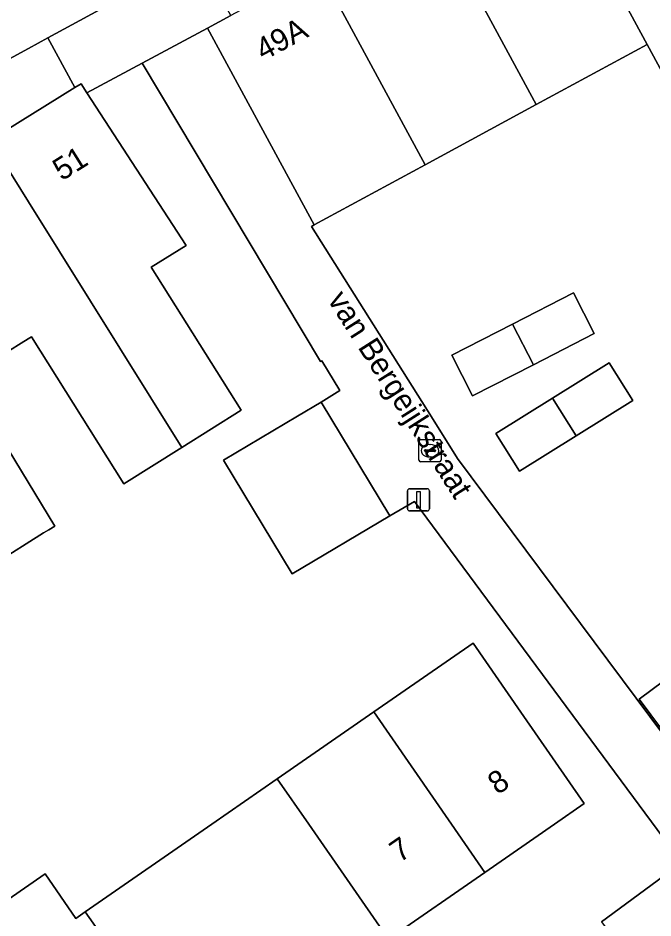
# Model space of a CAD drawing. Extents: x 161798 to 162385, y 382315 to 382833.
# Drawn here: x 161999.53 to 162028.08, y 382495.78 to 382536.26 of the extents above; entities that cross this region are included whole.
import ezdxf

# ---------------------------------------------------------------- set-up
doc = ezdxf.new("R2010")
doc.units = 0
for name, color, linetype in [('IMGEO_Erf', 7, 'Continuous'), ('IMGEO_Kolk', 7, 'Continuous'), ('IMGEO_Lichtmast', 7, 'Continuous'), ('IMGEO_Openbare_ruimte_label', 7, 'Continuous'), ('IMGEO_Pand', 7, 'Continuous'), ('IMGEO_Pand_nummerreeks', 7, 'Continuous'), ('IMGEO_Rijbaan_lokaal_open', 7, 'Continuous'), ('IMGEO_Voetpad_open', 7, 'Continuous')]:
    doc.layers.add(name, color=color, linetype=linetype)

msp = doc.modelspace()

# ---------------------------------------------------------------- linework, layer by layer
at = {"layer": 'IMGEO_Erf'}
for points in [[(162030.144, 382530.776), (162027.822, 382535.062), (162022.829, 382532.361), (162017.835, 382529.66), (162012.842, 382526.959), (162012.729, 382526.884), (162018.127, 382518.324), (162019.294, 382516.448), (162033.46, 382497.424)], [(162032.099, 382494.574), (162017.357, 382514.511), (162016.252, 382513.875), (162011.864, 382511.26), (162008.769, 382516.37), (162012.091, 382518.35), (162013.157, 382518.985), (162014.004, 382519.503), (162013.198, 382520.835), (162013.13, 382520.802), (162005.114, 382534.226), (162002.633, 382532.892), (162007.095, 382526.032), (162005.526, 382525.045), (162009.567, 382518.617), (162006.904, 382516.943), (162004.293, 382515.302), (162000.143, 382521.924), (161999.985, 382521.825), (161999.68, 382521.633), (161998.618, 382520.967)], [(161997.572, 382519.339), (162001.183, 382513.409), (162000.921, 382513.244), (162000.686, 382513.097), (161998.485, 382511.718)], [(162033.521, 382497.469), (162027.455, 382505.625), (162031.195, 382508.4)], [(162025.765, 382495.613), (162028.834, 382497.868)]]:
    msp.add_lwpolyline(points, dxfattribs=at)
for points in [[(162019.03, 382521.09), (162021.767, 382522.49), (162024.504, 382523.89), (162025.438, 382522.064), (162022.701, 382520.664), (162019.964, 382519.264)], [(162024.623, 382517.461), (162022.075, 382515.869), (162021.016, 382517.565), (162023.563, 382519.157), (162026.112, 382520.75), (162027.17, 382519.053)], [(161996.867, 382495.078), (162000.748, 382497.765), (162002.132, 382495.765), (162002.559, 382496.061), (162008.247, 382500), (162011.191, 382502.039), (162015.531, 382505.046), (162019.993, 382508.136), (162022.139, 382505.038), (162024.987, 382500.927), (162023.649, 382500), (162020.522, 382497.834), (162016.181, 382494.828), (162013.781, 382493.165), (162014.653, 382491.905), (162010.774, 382489.218), (162009.894, 382490.488), (162007.543, 382488.859), (162003.252, 382485.887), (161998.668, 382482.712), (161992.22, 382491.86)]]:
    msp.add_lwpolyline(points, close=True, dxfattribs=at)
at = {"layer": 'IMGEO_Kolk'}
for p, q in [((162017.628, 382517.297), (162018.48, 382517.297)), ((162017.553, 382516.371), (162017.553, 382517.223)), ((162018.041, 382517.077), (162018.066, 382517.077)), ((162018.554, 382517.223), (162018.554, 382516.371)), ((162017.812, 382516.791), (162017.812, 382516.803)), ((162018.25, 382516.754), (162017.852, 382516.754)), ((162017.855, 382516.84), (162018.253, 382516.84)), ((162018.064, 382516.517), (162018.039, 382516.517)), ((162018.296, 382516.803), (162018.296, 382516.791)), ((162018.48, 382516.297), (162017.628, 382516.297))]:
    msp.add_line(p, q, dxfattribs=at)
for points in [[(162017.628, 382517.297), (162018.48, 382517.297)], [(162017.553, 382516.371), (162017.553, 382517.223)], [(162018.554, 382517.223), (162018.554, 382516.371)], [(162018.48, 382516.297), (162017.628, 382516.297)]]:
    msp.add_lwpolyline(points, dxfattribs=at)
for centre, radius, start, end in [((162017.63, 382517.221), 0.0765, 91.552, 178.448), ((162017.63, 382517.221), 0.0765, 91.552, 178.448), ((162018.478, 382517.221), 0.0765, 1.552, 88.448), ((162018.478, 382517.221), 0.0765, 1.552, 88.448), ((162017.852, 382516.8), 0.0403, 85.8775, 175.7526), ((162017.849, 382516.79), 0.0366, 178.938, 274.7102), ((162018.253, 382516.797), 0.043, 264.8664, 352.4533), ((162018.257, 382516.802), 0.0386, 1.7309, 96.639), ((162017.63, 382516.373), 0.0765, 181.552, 268.448), ((162017.63, 382516.373), 0.0765, 181.552, 268.448), ((162018.478, 382516.373), 0.0765, 271.552, 358.448), ((162018.478, 382516.373), 0.0765, 271.552, 358.448)]:
    msp.add_arc(centre, radius, start, end, dxfattribs=at)
for centre, major_axis, ratio, start_param, end_param in [((162018.04, 382516.797), (-0.387, 0.002), 0.722429, 4.712389, 7.853982), ((162018.065, 382516.797), (-0.39, 0.002), 0.717154, 1.570796, 4.712389)]:
    msp.add_ellipse(centre, major_axis=major_axis, ratio=ratio, start_param=start_param, end_param=end_param, dxfattribs=at)
at = {"layer": 'IMGEO_Lichtmast'}
for p, q in [((162017.036, 382514.188), (162017.036, 382514.988)), ((162017.036, 382514.988), (162017.036, 382514.188)), ((162017.136, 382515.088), (162017.926, 382515.088)), ((162017.926, 382515.088), (162017.136, 382515.088)), ((162018.026, 382514.988), (162018.026, 382514.188)), ((162018.026, 382514.188), (162018.026, 382514.988)), ((162017.926, 382514.088), (162017.136, 382514.088)), ((162017.136, 382514.088), (162017.926, 382514.088))]:
    msp.add_line(p, q, dxfattribs=at)
msp.add_lwpolyline([(162017.456, 382514.963), (162017.606, 382514.963), (162017.606, 382514.213), (162017.456, 382514.213), (162017.456, 382514.963)], dxfattribs=at)
for centre, start, end in [((162017.136, 382514.988), 90, 180), ((162017.136, 382514.988), 90, 180), ((162017.926, 382514.988), 0, 90), ((162017.926, 382514.988), 360, 90), ((162017.136, 382514.188), 180, 270), ((162017.136, 382514.188), 180, 270), ((162017.926, 382514.188), 270, 0), ((162017.926, 382514.188), 270, 0)]:
    msp.add_arc(centre, 0.1, start, end, dxfattribs=at)
at = {"layer": 'IMGEO_Pand'}
for points in [[(162031.561, 382539.287), (162027.712, 382546.375), (162026.763, 382545.865), (162023.051, 382543.867), (162027.822, 382535.062), (162030.144, 382530.776), (162032.495, 382532.051), (162029.252, 382538.035)], [(162023.051, 382543.867), (162018.057, 382541.183), (162022.829, 382532.361), (162027.822, 382535.062)], [(162018.057, 382541.183), (162013.056, 382538.495), (162017.835, 382529.66), (162022.829, 382532.361)], [(162013.056, 382538.495), (162009.095, 382536.366), (162008.051, 382535.805), (162012.842, 382526.959), (162017.835, 382529.66)], [(162007.095, 382526.032), (162002.633, 382532.892), (162002.367, 382533.301), (162002.092, 382533.131), (161998.271, 382530.756), (162000, 382527.989), (162006.904, 382516.943), (162009.567, 382518.617), (162005.526, 382525.045)], [(161998.271, 382530.756), (161994.122, 382528.161), (161998.618, 382520.967), (161999.68, 382521.633), (161999.985, 382521.825), (162000.143, 382521.924), (162004.293, 382515.302), (162006.904, 382516.943), (162000, 382527.989)], [(161998.618, 382520.967), (161994.122, 382528.161), (161989.813, 382525.467), (161994.313, 382518.265), (161995.96, 382515.629), (161996.647, 382514.565), (161998.485, 382511.718), (162000.686, 382513.097), (162000.921, 382513.244), (162001.183, 382513.409), (161997.572, 382519.339), (161997.376, 382519.66), (161997.144, 382520.042)], [(162021.767, 382522.49), (162022.701, 382520.664), (162025.438, 382522.064), (162024.504, 382523.89)], [(162021.767, 382522.49), (162019.03, 382521.09), (162019.964, 382519.264), (162022.701, 382520.664)], [(162023.563, 382519.157), (162024.623, 382517.461), (162027.17, 382519.053), (162026.112, 382520.75)], [(162012.091, 382518.35), (162008.769, 382516.37), (162011.864, 382511.26), (162016.252, 382513.875), (162013.157, 382518.985)], [(162023.563, 382519.157), (162021.016, 382517.565), (162022.075, 382515.869), (162024.623, 382517.461)], [(162031.195, 382508.4), (162027.455, 382505.625), (162033.521, 382497.469), (162034.68, 382498.33), (162035.513, 382498.948), (162037.25, 382500.238)], [(162015.531, 382505.046), (162019.023, 382500), (162020.522, 382497.834), (162023.649, 382500), (162024.987, 382500.927), (162022.139, 382505.038), (162019.993, 382508.136)], [(162016.181, 382494.828), (162020.522, 382497.834), (162019.023, 382500), (162015.531, 382505.046), (162011.191, 382502.039), (162012.602, 382500)], [(162012.602, 382500), (162011.191, 382502.039), (162008.247, 382500), (162002.559, 382496.061), (162003.194, 382495.144), (162007.543, 382488.859), (162009.894, 382490.488), (162010.774, 382489.218), (162014.653, 382491.905), (162013.781, 382493.165), (162016.181, 382494.828)], [(162027.591, 382493.128), (162030.66, 382495.383), (162028.834, 382497.868), (162025.765, 382495.613)], [(162002.559, 382496.061), (162002.132, 382495.765), (162000.748, 382497.765), (161996.867, 382495.078), (161998.269, 382493.089), (162003.252, 382485.887), (162007.543, 382488.859), (162003.194, 382495.144)]]:
    msp.add_lwpolyline(points, close=True, dxfattribs=at)
at = {"layer": 'IMGEO_Rijbaan_lokaal_open'}
msp.add_lwpolyline([(162005.658, 382541.95), (162002.236, 382540.051), (162000, 382538.811), (161998.314, 382537.876), (161991.203, 382533.931), (161985.491, 382530.651), (161979.276, 382527.063), (161953.15, 382510.607), (161949.145, 382508.117), (161948.095, 382507.457), (161949.963, 382504.519), (161955.014, 382507.648), (161956.057, 382508.297), (161979.411, 382522.988), (161986.125, 382527.031), (161996.967, 382533.235), (162000, 382534.889), (162000.874, 382535.365), (162007.323, 382538.877)], close=True, dxfattribs=at)
at = {"layer": 'IMGEO_Voetpad_open'}
msp.add_lwpolyline([(162008.051, 382535.805), (162009.095, 382536.366), (162007.62, 382539.039), (162007.323, 382538.877), (162000.874, 382535.365), (162002.092, 382533.131), (162002.367, 382533.301), (162002.633, 382532.892), (162005.114, 382534.226)], close=True, dxfattribs=at)
for points in [[(162033.46, 382497.424), (162019.294, 382516.448), (162018.127, 382518.324), (162012.729, 382526.884), (162012.842, 382526.959), (162008.051, 382535.805), (162005.114, 382534.226), (162013.13, 382520.802), (162013.198, 382520.835), (162014.004, 382519.503), (162013.157, 382518.985), (162016.252, 382513.875), (162017.357, 382514.511), (162032.099, 382494.574)], [(161957.613, 382506.446), (161958.095, 382505.71), (161968.068, 382512.042), (161968.153, 382511.883), (161969.132, 382512.557), (161974, 382515.595), (161979.401, 382518.966), (161979.504, 382518.791), (161980.496, 382519.538), (161981.298, 382520.142), (161985.691, 382522.889), (161989.813, 382525.467), (161994.122, 382528.161), (161998.271, 382530.756), (162002.092, 382533.131), (162000.874, 382535.365), (162000, 382534.889), (161996.967, 382533.235)]]:
    msp.add_lwpolyline(points, dxfattribs=at)

# ---------------------------------------------------------------- texts
at = {"layer": 'IMGEO_Openbare_ruimte_label'}
msp.add_text('van Bergeijkstraat', height=1, rotation=302.5459, dxfattribs=at).set_placement((162013.424, 382523.584))
at = {"layer": 'IMGEO_Pand_nummerreeks'}
for s, rotation, p in [('49A', 28.2583, (162010.56, 382534.315)), ('51', 32.0169, (162001.5, 382528.906)), ('8', 34.7102, (162021.096, 382501.297)), ('7', 34.7081, (162016.69, 382498.246))]:
    msp.add_text(s, height=1, rotation=rotation, dxfattribs=at).set_placement(p)

doc.saveas('drawing.dxf')
